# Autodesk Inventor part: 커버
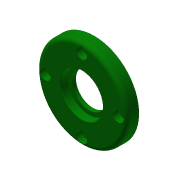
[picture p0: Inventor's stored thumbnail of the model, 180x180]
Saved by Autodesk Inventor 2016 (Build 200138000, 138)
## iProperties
Created: 2019-09
Part Number: 커버
Material: 알루미늄 6061
Document SubType Name: Modeling
Designer: mduedu
Density: 2.71 g/cm^3
Mass: 60.8496 g
Surface Area: 89.5893 cm^2
Volume: 22.4537 cm^3
Appearance: 진녹색
Author: mduedu
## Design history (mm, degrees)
sketch "스케치1"
  geometry: C1 r 32 at (0, 0); 1 further point
  constraints: 1 centre point, 1 coincident
  dimensions: "d0" = 64 diameter of C1
extrude "돌출1" new body sketch "스케치1" distance "d1" = 9; taper "d2" = 0 deg
sketch "스케치2"
  geometry: C1 r 21 at (0, 0); 1 further point
  constraints: 1 centre point, 1 coincident
  dimensions: "d3" = 42 diameter of C1
extrude "돌출2" join sketch "스케치2" distance "d4" = 3; taper "d5" = 0 deg
hole "구멍1" diameter "d8" = 24; stored, may be unused: countersink angle "d12" = 90 deg, drill point angle "d14" = 118 deg; dims "d6" = 10, "d7" = 10, "d9" = 6, "d10" = 30, "d11" = 5.2, "d13" = 8
hole "구멍2" diameter "d17" = 37; stored, may be unused: countersink angle "d21" = 90 deg, drill point angle "d23" = 0 deg; dims "d15" = 10, "d16" = 10, "d18" = 6, "d19" = 30, "d20" = 5.2, "d22" = 4
fillet "모깎기1" dims "d24" = 3
fillet "모깎기2" dims "d25" = 3
chamfer "모따기1" distance "d27" = 0.5; stored, may be unused: second distance "d28" = 2, angle "d29" = 30 deg
chamfer "모따기2" distance "d30" = 1; stored, may be unused: second distance "d31" = 2, angle "d32" = 30 deg
sketch "스케치3" dims "d33" = 52
  geometry: 3 further points
  constraints: 2 vertical alignment, 1 coincident, 2 other
hole "구멍3" sketch "스케치3" at (0, 26) diameter "d34" = 4.5; stored, may be unused: countersink angle "d38" = 90 deg, drill point angle "d40" = 0 deg; dims "d35" = 6, "d36" = 8, "d37" = 4.4, "d39" = 4
node "솔리드1"
pattern_circular "원형 패턴1" dims angle "d42" = 360 deg
